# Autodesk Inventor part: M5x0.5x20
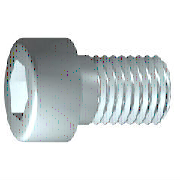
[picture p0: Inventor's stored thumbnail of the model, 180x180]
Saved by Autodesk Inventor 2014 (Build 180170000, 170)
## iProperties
IsCustomPart: 0
Company: 한국ATC센터
Created: 2009-02
Part Number: M5x0.5x20
Material: Steel, Mild
Description: 6각머리 태핑 나사
Document SubType Name: Modeling
Standard: KS B 1003
Designer: KYOUNG IL JANG
Standards Organization: KS
Language: ko-KR
Size Designation: M 5 x 20
Categories: <MemberInstance><Categories><Category DisplayName="조임쇠" InternalName="e4da775c-781d-43d5-af7c-5136215cf5a6" Mnemonic="FSTN"><Category DisplayName="볼트" InternalN
Density: 7.86 g/cm^3
Mass: 4.9629 g
Surface Area: 5.88238 cm^2
Volume: 0.631412 cm^3
Appearance: Metal-Steel
Author: KYOUNG IL JANG
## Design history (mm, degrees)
sketch "스케치1"
  geometry: L1 (-1.167, 0)-(20, 0); L2 (20, 0)-(20, 2.5); L3 (20, 2.5)-(2, 2.5); L4 (2, 2.5)-(1.509, 2.5); L5 (1.509, 2.5)-(0, 2.5); L6 (0, 2.5)-(0, 4.25); L7 (0, 4.25)-(-5, 4.25); L8 (-5, 4.25)-(-5, 2.309); L9 (-5, 2.309)-(-2.5, 2.309); L10 (-2.5, 2.309)-(-1.167, 0); L11 (-10, 0)-(25, 0) reference; L12 (0, -0.85)-(0, 5.1) reference; L13 (2, 2.5)-(0, 2.5)
  constraints: 22 end point, 6 parallel, 2 collinear, 2 perpendicular, 1 horizontal, 1 point on line
  dimensions: "d1" = 18 distance from line of L3.end L2 (= GEL); "d2" = 0.49086 distance of L4.end L3.end (computed from GAL); "d3" = 5 distance between parallel lines of L8 L6 (= KOH); "d4" = 2.5 distance of L8.end L9.end (= INTI); "d5" = 60 deg angle of L10 L1; "d6" = 5 diameter of L3 L1 (= GD); "d7" = 5 diameter of L5 L1 (= BDM); "d8" = 4.6188 diameter of L9 L1 (= 1.1547 x SW); "d9" = 8.5 diameter of L7 L1 (= KOD); "d26" = 20 distance between parallel lines of L12 L2 (= NLG)
revolve "본체" sketch "스케치1" stored, may be unused: angle "d10" = 90 deg
sketch "스케치2"
  geometry: L1 (0, -5.95)-(0, 5.95) reference; L2 (-5.95, 0)-(5.95, 0) reference; L3 (2.309, 0)-(1.155, -2); L4 (1.155, -2)-(-1.155, -2); L5 (-1.155, -2)-(-2.309, 0); L6 (-2.309, 0)-(-1.155, 2); L7 (-1.155, 2)-(1.155, 2); L8 (1.155, 2)-(2.309, 0); 2 further points
  constraints: 12 end point, 1 coincident, 1 horizontal alignment, 1 point on line, 12 other
extrude "슬롯" join sketch "스케치2" stored distance "d11" = 10; taper "d12" = 0 deg
workplane "Work Plane1"
fillet "Fillet2" dims "d30" = 0.1 (= R)
body "Solid1"
fillet "모깎기1" dims "d17" = 0.5 (= RR)
feature "스레드" dims "d13" = 18 (= GEL), "d14" = 0
chamfer "모따기1" distance "d15" = 0.49076 (= -0.5 x SPD + 0.5 x GD); stored, may be unused: second distance "d16" = 0.49076 (= GUL), angle "d27" = 45 deg
other parameters: "GD" = 5 (= NND) [user parameter; used in 2 equation terms], "NLG" = 20 [user parameter; used in 1 equation term], "GEL" = 18 [user parameter; used in 2 equation terms], "KOD" = 8.5 [user parameter; used in 1 equation term], "KOH" = 5 [user parameter; used in 1 equation term], "INTI" = 2.5 [user parameter; used in 1 equation term], "GAL" = 0.49076 (= 0.61345 x PTC) [user parameter; used in 1 equation term], "GUL" = 0.49076 (= 0.61345 x PTC) [user parameter; used in 1 equation term], "BDM" = 5 (= NND) [user parameter; used in 1 equation term], "SW" = 4 [user parameter; used in 2 equation terms], "RR" = 0.5 [user parameter; used in 1 equation term], "SPD" = 4.01848 (= NND - 1.2269 x PTC) [user parameter; used in 1 equation term], "d19" = 0, "d28" = 0, "d29" = 0, "R" = 0.1 [user parameter; used in 1 equation term], "PHH" = 0.2 [user parameter], "GD1" = 4.01848 (= THREADDIA - 1.2269 x PTC) [user parameter], "THREADDIA" = 5 [user parameter; used in 1 equation term], "FAWI" = 45 deg [user parameter], "TPU" = 12.5 (computed from PTC) [user parameter], "PTC" = 0.8 [user parameter; used in 5 equation terms], "NND" = 5 [user parameter; used in 3 equation terms], "TOA" = 30 deg [user parameter], "E0" = 4.62 (= 1.155 x SW) [user parameter]
